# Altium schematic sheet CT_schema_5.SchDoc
size 577 x 363 mm
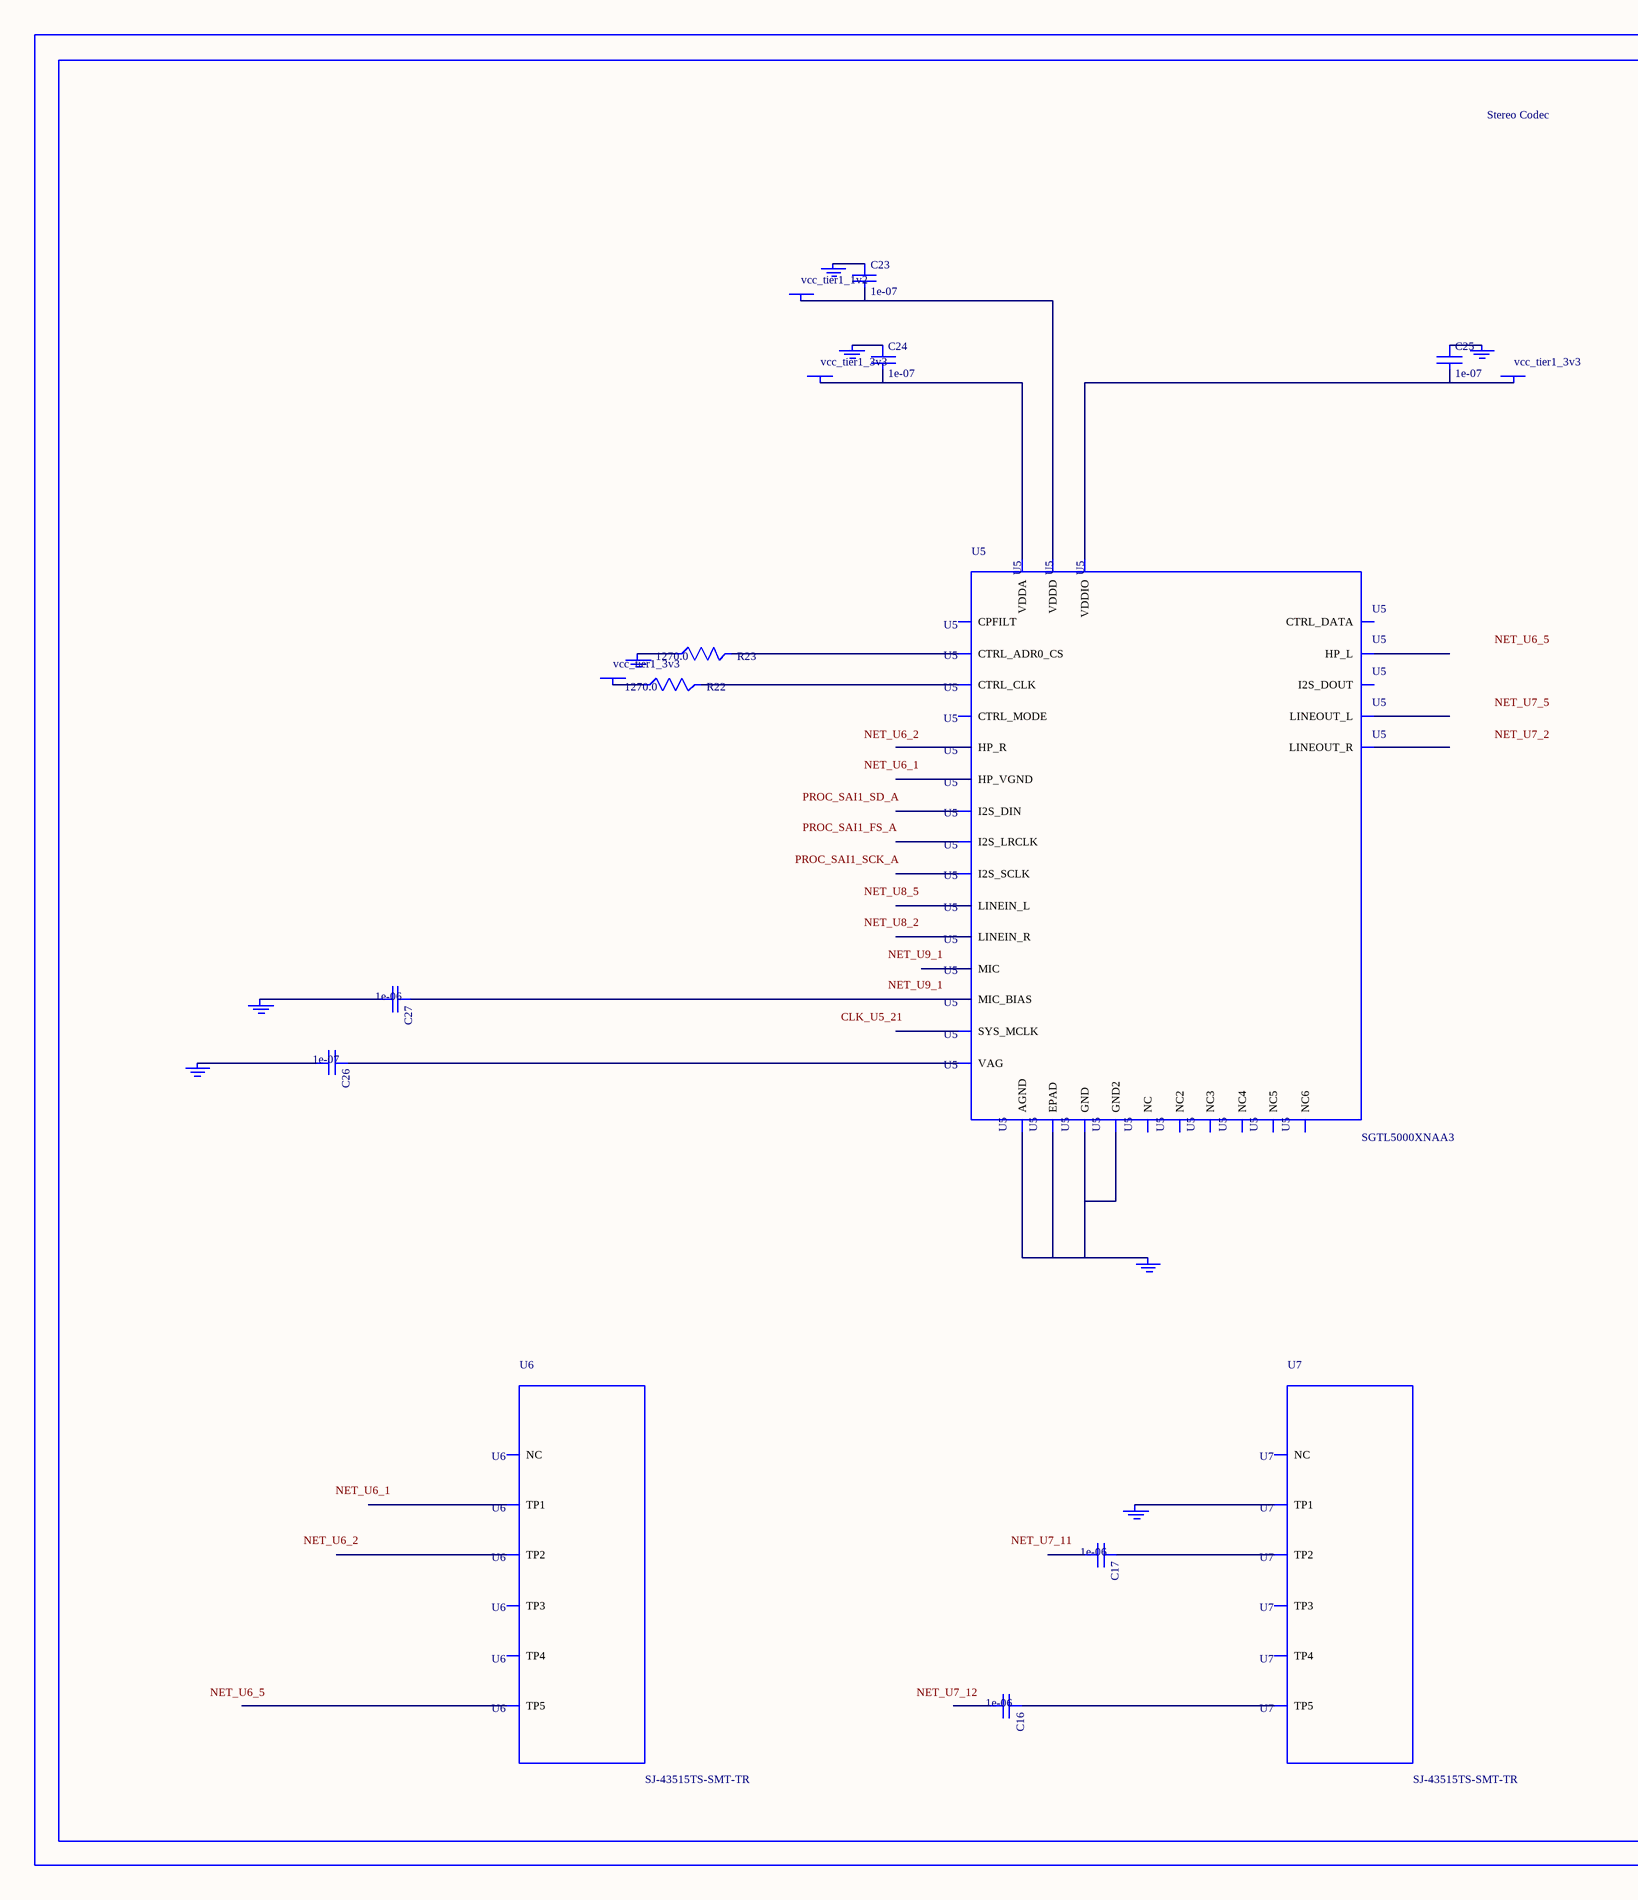
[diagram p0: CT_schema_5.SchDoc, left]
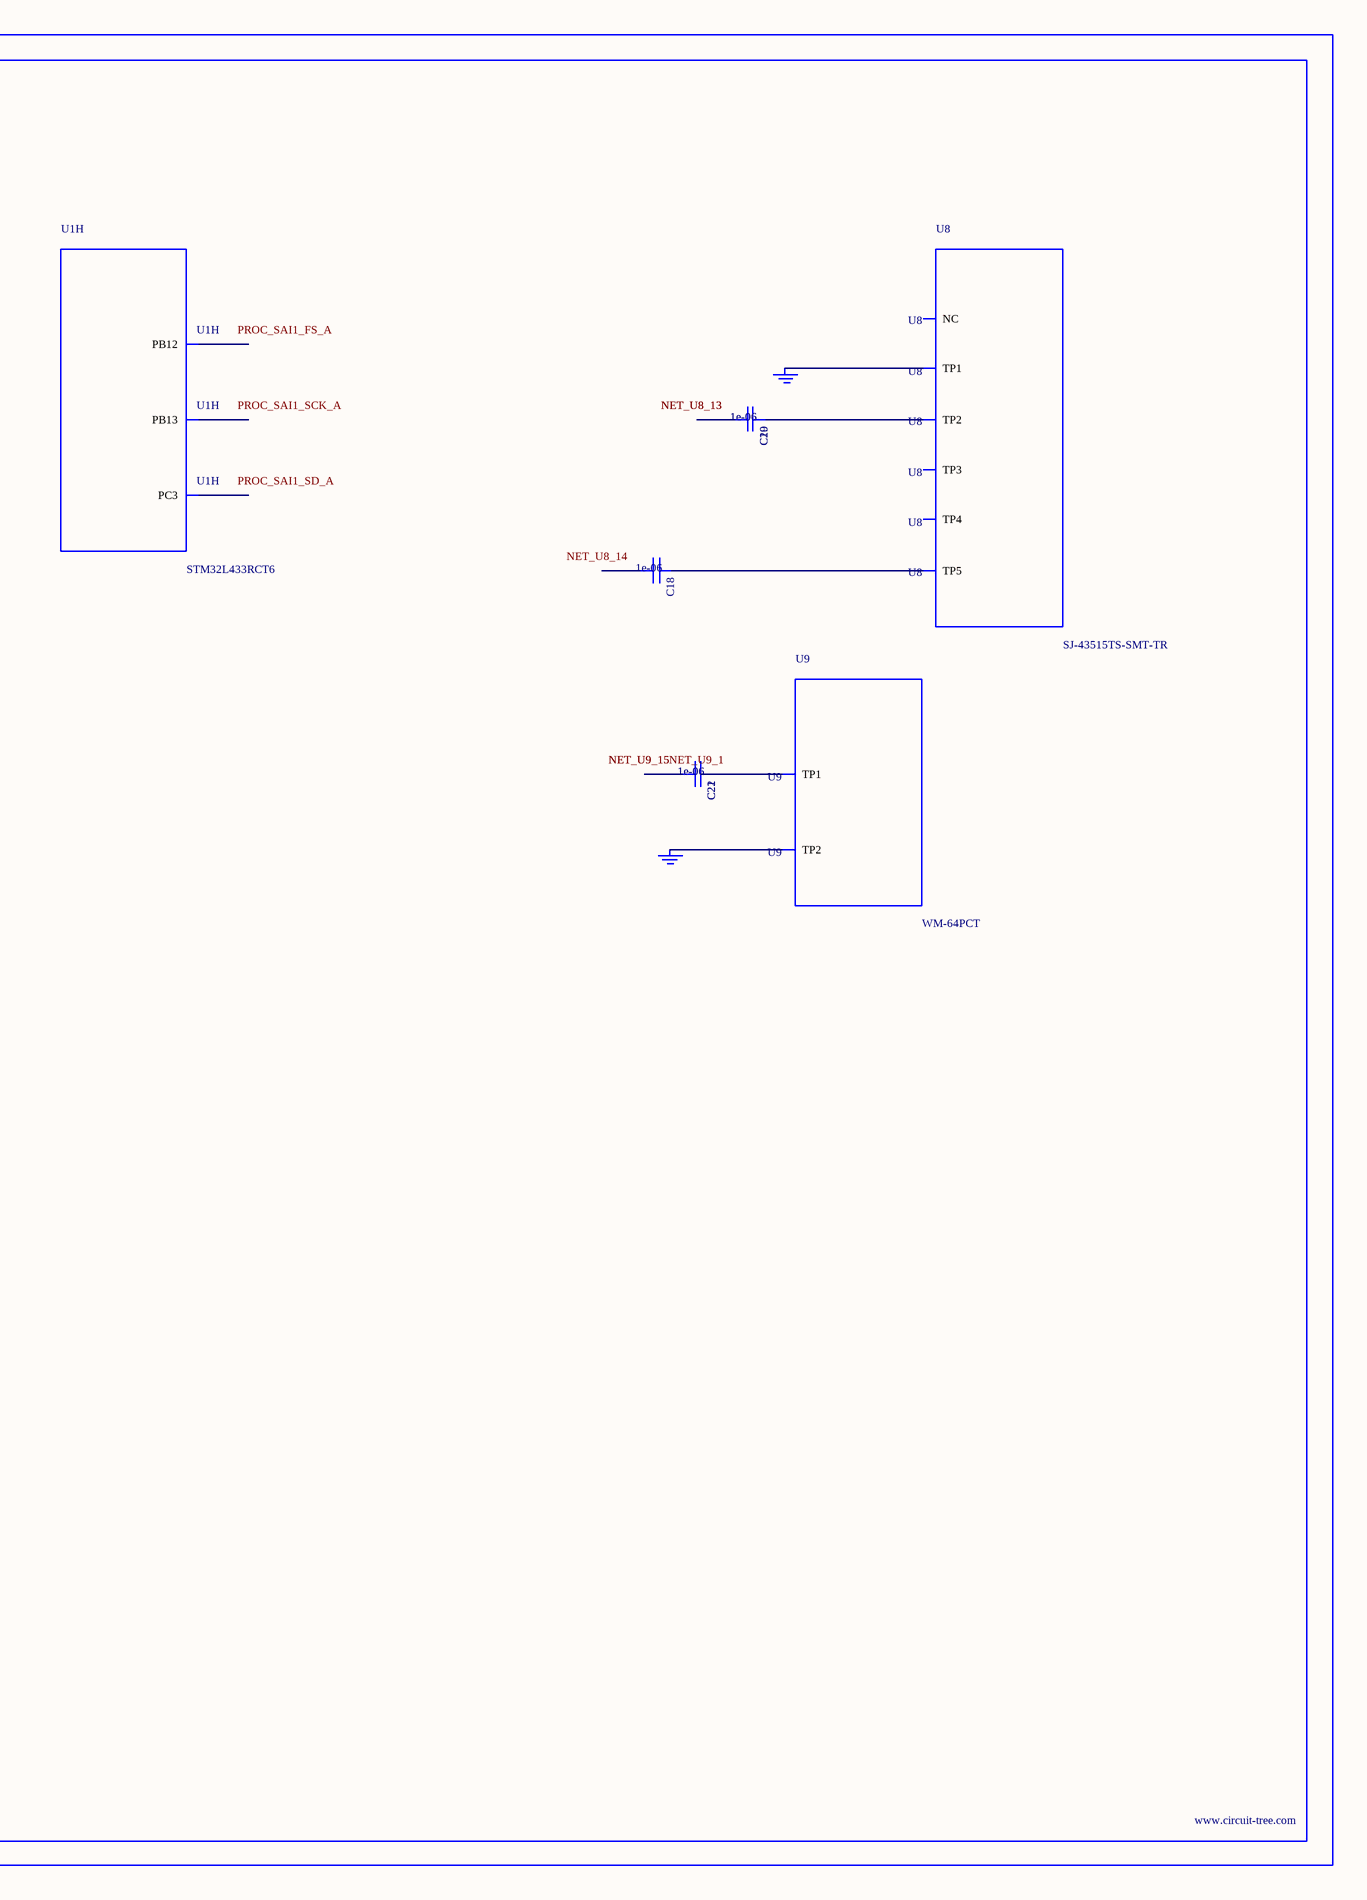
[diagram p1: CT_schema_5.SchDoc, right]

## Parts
BORDER4  (no value)
C16  1e-06  [C0603]
C17  1e-06  [C0603]
C18  1e-06  [C0603]
C19  1e-06  [C0603]
C20  1e-06  [C0603]
C21  1e-06  [C0603]
C22  1e-06  [C0603]
C23  1e-07  [C0402]
C24  1e-07  [C0402]
C25  1e-07  [C0402]
C26  1e-07  [C0402]
C27  1e-06  [C0603]
GND_INSTANCE_4_0  (no value)
GND_INSTANCE_4_1  (no value)
GND_INSTANCE_4_2  (no value)
GND_INSTANCE_4_3  (no value)
GND_INSTANCE_4_4  (no value)
GND_INSTANCE_4_5  (no value)
GND_INSTANCE_4_6  (no value)
GND_INSTANCE_4_7  (no value)
GND_INSTANCE_4_8  (no value)
GND_INSTANCE_4_9  (no value)
GND_INSTANCE_4_10  (no value)
POWER_INSTANCE_4_0  vcc_tier1_3v3
POWER_INSTANCE_4_1  vcc_tier1_3v3
POWER_INSTANCE_4_2  vcc_tier1_3v3
POWER_INSTANCE_4_3  vcc_tier1_1v2
R22  1270.0  [R0603]
R23  1270.0  [R0603]
U1  STM32L433RCT6  [LQFP64]  (part H of 8)
U5  SGTL5000XNAA3  [QFN-32]
U6  SJ-43515TS-SMT-TR  [SJ-43515TS-SMT-TR]
U7  SJ-43515TS-SMT-TR  [SJ-43515TS-SMT-TR]
U8  SJ-43515TS-SMT-TR  [SJ-43515TS-SMT-TR]
U9  WM-64PCT  [WM-64PC]

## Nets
NetC16_1: C16.1 U7.5(TP5)
NetC17_1: C17.1 U7.2(TP2)
NetC18_1: C18.1 U8.5(TP5)
NetC19_1: C19.1 C20.1 U8.2(TP2)
NetC19_2: C19.2 C20.2
NetC21_1: C21.1 C22.1 U9.1(TP1)
NetC21_2: C21.2 C22.2
NetC23_1: C23.1 GND_INSTANCE_4_5.0(GND)
NetC23_2: C23.2 POWER_INSTANCE_4_3.0(PWR) U5.30(VDDD)
NetC24_1: C24.1 GND_INSTANCE_4_1.0(GND)
NetC24_2: C24.2 POWER_INSTANCE_4_0.0(PWR) U5.5(VDDA)
NetC25_1: C25.1 GND_INSTANCE_4_4.0(GND)
NetC25_2: C25.2 POWER_INSTANCE_4_1.0(PWR) U5.20(VDDIO)
NetC26_1: C26.1 U5.10(VAG)
NetC26_2: C26.2 GND_INSTANCE_4_2.0(GND)
NetC27_1: C27.1 U5.16(MIC_BIAS)
NetC27_2: C27.2 GND_INSTANCE_4_3.0(GND)
NetGND_INSTANCE_4_0_0: GND_INSTANCE_4_0.0(GND) U5.1(GND) U5.3(GND2) U5.7(AGND) U5.EXP(EPAD)
NetGND_INSTANCE_4_6_0: GND_INSTANCE_4_6.0(GND) R23.1
NetGND_INSTANCE_4_7_0: GND_INSTANCE_4_7.0(GND) U7.1(TP1)
NetGND_INSTANCE_4_8_0: GND_INSTANCE_4_8.0(GND) GND_INSTANCE_4_9.0(GND) U8.1(TP1)
NetGND_INSTANCE_4_10_0: GND_INSTANCE_4_10.0(GND) U9.2(TP2)
NetPOWER_INSTANCE_4_2_0: POWER_INSTANCE_4_2.0(PWR) R22.1
NetR22_2: R22.2 U5.29(CTRL_CLK)
NetR23_2: R23.2 U5.31(CTRL_ADR0_CS)

Not connected (* = marked no-connect by the designer): C16 2; C17 2; C18 2; U1 11(PC3) 33(PB12) 34(PB13); U5 2(HP_R) 4(HP_VGND) 6(HP_L) 8(NC) 9(NC2) 11(LINEOUT_R) 12(LINEOUT_L) 13(LINEIN_R) 14(LINEIN_L) 15(MIC) 17(NC3) 18(CPFILT) 19(NC4) 21(SYS_MCLK) 22(NC5) 23(I2S_LRCLK) 24(I2S_SCLK) 25(I2S_DOUT) 26(I2S_DIN) 27(CTRL_DATA) 28(NC6) 32(CTRL_MODE); U6 1(TP1) 2(TP2) 3(TP3) 4(TP4) 5(TP5) 6(NC); U7 3(TP3) 4(TP4) 6(NC); U8 3(TP3) 4(TP4) 6(NC)

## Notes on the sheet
- Labels drawn without touching a wire or pin: CLK_U5_21, NET_U6_1, NET_U6_2, NET_U6_5, NET_U7_2, NET_U7_5, NET_U7_11, NET_U7_12, NET_U8_2, NET_U8_5, NET_U8_14, NET_U9_1, PROC_SAI1_FS_A, PROC_SAI1_SCK_A, PROC_SAI1_SD_A

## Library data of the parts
BORDER4 = BORDER_PAGE4
C16-C22 C27 = C0603C105K3RACTU
C23-C26 = C0402C104K3RACTU
GND_INSTANCE_4_0-GND_INSTANCE_4_10 = GND
POWER_INSTANCE_4_0-POWER_INSTANCE_4_3 = PWR
R22 R23 = RC0603FR-071K27L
